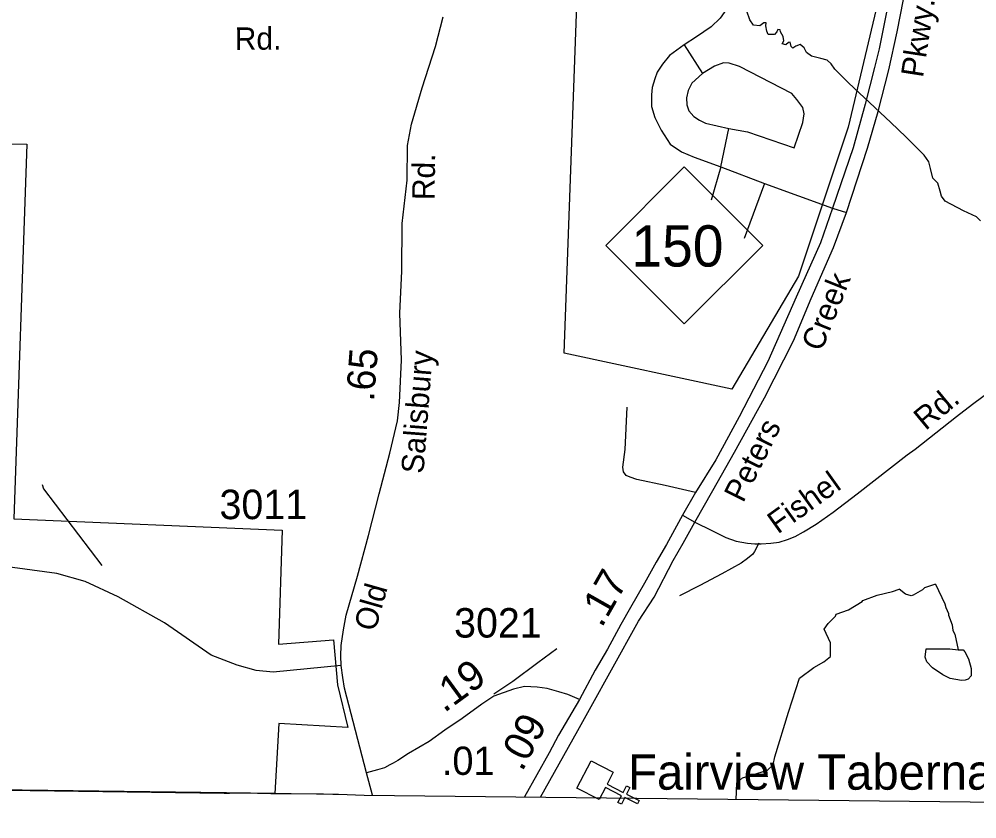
# Model space of a CAD drawing. Extents: x 1547597 to 1699558, y 810033 to 920809.
# Drawn here: x 1623103 to 1627167, y 819952 to 823344 of the extents above; entities that cross this region are included whole.
import ezdxf

# ---------------------------------------------------------------- set-up
doc = ezdxf.new("R2010")
doc.units = 0
for name, color, linetype in [('Exist Boundary Political City Limit New', 7, 'Continuous'), ('Exist Boundary Political CountyLine', 7, 'Continuous'), ('Exist Cultural Church CELL', 7, 'Continuous'), ('Exist Cultural Church Label', 7, 'Continuous'), ('Exist Hydrographic Creek Single Shore', 7, 'Continuous'), ('Exist Hydrographic Misc Water Feature', 7, 'Continuous'), ('Exist Road Non-System Type 51', 7, 'Continuous'), ('Exist Road Primary NC Divided Attributed', 7, 'Continuous'), ('Exist Road Primary NC Label', 7, 'Continuous'), ('Exist Road Primary NC Service Mileage Hundredths English Label', 7, 'Continuous'), ('Exist Road Primary NC Shield CELL', 7, 'Continuous'), ('Exist Road Primary NC Shield Number Label', 7, 'Continuous'), ('Exist Road Secondary Mileage Hundredths English Label', 7, 'Continuous'), ('Exist Road Secondary Type 51 Attributed', 7, 'Continuous'), ('Exist Road Secondary Type 51 Label', 7, 'Continuous'), ('Exist Road Secondary Type 51 Number Label', 7, 'Continuous'), ('Map Preparation Boundary City Limit Buffer Line', 7, 'Continuous')]:
    doc.layers.add(name, color=color, linetype=linetype)

msp = doc.modelspace()

# ---------------------------------------------------------------- linework, layer by layer
at = {"layer": 'Exist Boundary Political City Limit New'}
for points in [[(1624585.1, 825934.1), (1626899.2, 825873.3), (1626810, 823882.4), (1626744.7, 823409.9), (1626621.2, 822886.4), (1626410.5, 822253.9), (1626127.2, 821774), (1625415.4, 821926.7), (1625488, 823911.5), (1625546.1, 823940.6), (1625577.9, 824608.7), (1625332.2, 824717.2), (1625335.8, 825346.1), (1624345.6, 825299.1), (1624349.2, 825176.2), (1624287.8, 825349.7), (1624443.2, 825711.2), (1624585.1, 825934.1)], [(1622237.9, 822828.2), (1623135.5, 822813.7), (1623080, 821224.5), (1624219.3, 821176.2), (1624203.5, 820692.6), (1624436.5, 820710.6), (1624454.3, 820520.6), (1624498.1, 820339.4), (1624204.6, 820355.8), (1624188.1, 820058.9)], [(1624188.1, 820058.9), (1623982.5, 820061.2), (1621271.1, 820096.9)]]:
    msp.add_lwpolyline(points, dxfattribs=at)
at = {"layer": 'Exist Boundary Political CountyLine'}
msp.add_lwpolyline([(1606492.6, 820282.1), (1613860.9, 820194.5), (1614148.1, 820194.4), (1614278.7, 820193.7), (1614685.6, 820195), (1614832.4, 820191.9), (1615113.9, 820191.3), (1615321.1, 820189.2), (1615424.8, 820185.5), (1615839, 820171.5), (1623973.3, 820060), (1623995.2, 820060.7), (1624042.9, 820061.2), (1624114.1, 820060.5), (1624171.2, 820059.7), (1624213.4, 820059.1), (1624257.5, 820058.7), (1624364.8, 820057.3), (1624394.8, 820056.9), (1624433.9, 820056.2), (1624457.5, 820055.9), (1624566.7, 820052.4), (1633697.6, 819951.5)], dxfattribs=at)
at = {"layer": 'Exist Cultural Church CELL'}
msp.add_lwpolyline([(1625624.1, 820149.1), (1625598.1, 820098.4), (1625665.9, 820063.6), (1625680.5, 820092.1), (1625694.7, 820084.8), (1625680.1, 820056.3), (1625733.6, 820028.8), (1625726.2, 820014.6), (1625672.7, 820042), (1625658.1, 820013.6), (1625643.9, 820020.9), (1625658.5, 820049.3), (1625590.8, 820084.1), (1625564.4, 820032.9), (1625469.7, 820081.6), (1625529.4, 820197.7)], close=True, dxfattribs=at)
at = {"layer": 'Exist Hydrographic Creek Single Shore'}
for points in [[(1627182.1, 822488.9), (1627165.5, 822505.5), (1627110.6, 822531.5), (1627032.6, 822572.5), (1627017, 822593.5), (1627010.4, 822614.6), (1627001, 822647.8), (1626979.4, 822669.4), (1626970, 822710.9), (1626962.8, 822739.2), (1626942.8, 822767.4), (1626864.8, 822844.4), (1626802.2, 822905.3), (1626622.2, 823074.2), (1626564.6, 823131.3), (1626548, 823154.5), (1626531.4, 823169.5), (1626504.2, 823177.8), (1626464.4, 823187.8), (1626443.3, 823202.2), (1626433.4, 823222.6), (1626416.7, 823236.5), (1626399, 823229.3), (1626385.2, 823221.5), (1626379.1, 823227.6), (1626374.1, 823245.9), (1626366.9, 823244.8), (1626356.4, 823234.8), (1626340.9, 823239.8), (1626348.1, 823252), (1626345.3, 823270.3), (1626333.7, 823290.2), (1626331.5, 823299.1), (1626322.6, 823300.7), (1626317.6, 823290.2), (1626307.7, 823279.1), (1626281.6, 823279.7), (1626275.5, 823293), (1626271.1, 823316.2), (1626272.2, 823328.4), (1626262.2, 823328.4), (1626245.6, 823316.2), (1626219, 823319), (1626203, 823340.6), (1626190.8, 823377.7)], [(1623199.8, 821369.5), (1623206.7, 821351.4), (1623453.1, 821025.6)]]:
    msp.add_lwpolyline(points, dxfattribs=at)
at = {"layer": 'Exist Hydrographic Misc Water Feature'}
for points in [[(1626144.9, 820032.7), (1626148.1, 820103.7), (1626172.8, 820125.5), (1626232.5, 820144.4), (1626279, 820157.5), (1626302.3, 820180.8), (1626309.8, 820215), (1626367.8, 820404.4), (1626413.7, 820548), (1626474.8, 820593.8), (1626517.6, 820618.2), (1626545.1, 820639.6), (1626545.1, 820697.7), (1626519.4, 820756.7), (1626535.8, 820780.4), (1626566.3, 820811.9), (1626570.4, 820819.8), (1626622.7, 820838.8), (1626680.6, 820873.1), (1626683.4, 820877.7), (1626743.8, 820900.6), (1626808.1, 820915.5), (1626837.3, 820926.1)], [(1626990.6, 820946.9), (1626944.3, 820931), (1626936.2, 820923.1), (1626895.8, 820899.9), (1626887.7, 820898), (1626863.9, 820904.5), (1626837.3, 820926.1)], [(1626990.6, 820946.9), (1627031.2, 820863.5), (1627035, 820847.5), (1627046.6, 820823.3), (1627046.5, 820815.3), (1627061.7, 820775), (1627065.3, 820751), (1627073.1, 820734.9), (1627086.8, 820668.4)], [(1627086.8, 820668.4), (1627108, 820668.3), (1627115.9, 820660.2), (1627131.3, 820629.9), (1627142.7, 820589.8), (1627142.1, 820557.8), (1627129.9, 820544.1), (1627117.8, 820540.3), (1627101.8, 820538.6), (1627053.9, 820547.4), (1627022.2, 820561.9), (1626978.7, 820592.7), (1626955.1, 820617.1), (1626947.4, 820637.2), (1626951, 820672.8), (1626964, 820672.9), (1627052.1, 820673.3), (1627086.8, 820668.4)]]:
    msp.add_lwpolyline(points, dxfattribs=at)
at = {"layer": 'Exist Road Non-System Type 51'}
for p, q in [((1625925.3, 823235.8), (1626002.7, 823113.5)), ((1626080.2, 822717.9), (1626113.8, 822880.6)), ((1626080.2, 822717.9), (1626039.8, 822576.5)), ((1626080.2, 822717.9), (1626265.3, 822647.2)), ((1626265.3, 822647.2), (1626178.9, 822413.7)), ((1626265.3, 822647.2), (1626554.6, 822542)), ((1626554.6, 822542), (1626613.9, 822523.8))]:
    msp.add_line(p, q, dxfattribs=at)
for points in [[(1626208.1, 823601.1), (1626141.9, 823463.1), (1626104.8, 823386.8), (1626077.9, 823348.6), (1626038.6, 823311.6), (1625976.9, 823269.5), (1625925.3, 823235.8)], [(1625925.3, 823235.8), (1625862.4, 823189.8), (1625832.1, 823152.8), (1625810.8, 823119.1), (1625800.7, 823091), (1625789.5, 823054), (1625786.1, 823023.7), (1625786.1, 822974.3), (1625799.6, 822926.6), (1625826.5, 822872.8), (1625864.7, 822813.3)], [(1626392.1, 822798.7), (1626428.1, 822905.9), (1626433.7, 822941.8), (1626428.1, 822969.8), (1626403.4, 823003.5), (1626382, 823028.2), (1626159.8, 823142.7), (1626115, 823157.2), (1626091.4, 823158.4), (1626053.2, 823144.9), (1626002.7, 823113.5)], [(1626002.7, 823113.5), (1625956.7, 823072.5), (1625941, 823041.1), (1625934.3, 823010.8), (1625935.4, 822980.5), (1625944.4, 822955.8), (1625965.7, 822931.1), (1625990.4, 822915.4), (1626015.1, 822903.1), (1626113.8, 822880.6)], [(1626113.8, 822880.6), (1626193.5, 822866), (1626392.1, 822798.7)], [(1625864.7, 822813.3), (1625912.9, 822781.8), (1625966.8, 822758.3), (1626080.2, 822717.9)], [(1625972.1, 821335.4), (1625844.6, 821365.3), (1625724, 821391.2), (1625694.9, 821400.4), (1625678.1, 821408), (1625667.4, 821423.3), (1625664.4, 821443.2), (1625674.3, 821518), (1625683.5, 821698.3)], [(1626242.2, 821121.2), (1626223.1, 821086.1), (1626216.8, 821073.8), (1626192.8, 821055.4), (1626167.2, 821036.1), (1626084.4, 820991.3), (1625991.8, 820940.8), (1625905.1, 820898.1)], [(1624469.1, 820601.6), (1624180.2, 820574.4), (1624108.3, 820581.1), (1624027.5, 820603.5), (1623917.6, 820646.2), (1623720, 820783.1), (1623522.5, 820893.1), (1623383.4, 820958.2), (1623262.2, 820991.8), (1623022, 821025.5)], [(1625116.6, 820482.5), (1625197.6, 820535.3), (1625303.2, 820614.2), (1625383.8, 820673.8)]]:
    msp.add_lwpolyline(points, dxfattribs=at)
at = {"layer": 'Exist Road Primary NC Divided Attributed'}
for points in [[(1625969.8, 821210.2), (1626046.3, 821344.8), (1626138.2, 821507.6), (1626265, 821737.4), (1626388, 821979.4), (1626463.8, 822159.4), (1626559.1, 822375.4), (1626613.9, 822523.8), (1626703.1, 822796.2), (1626747.9, 822953), (1626792.8, 823129.1), (1626828.2, 823290.2), (1626868.1, 823494.6), (1626907.4, 823776.4), (1626926.2, 823925.4), (1626935.1, 824050), (1626956.7, 824516.8), (1626989.2, 825152.1), (1627009.8, 825594.5), (1627038.6, 826219.7), (1627059.1, 826636.7), (1627088.5, 827252)], [(1627021.5, 827250.3), (1627004.3, 826710.9), (1626949.5, 825591.7), (1626930.1, 825208), (1626896.9, 824515.2), (1626847.6, 823786.9), (1626799.5, 823454.6), (1626782.2, 823366.1), (1626752.3, 823218.8), (1626731.8, 823139.6), (1626693.1, 822983.4), (1626642.1, 822797.9), (1626554.6, 822542), (1626503.1, 822395.3), (1626400.1, 822164.4), (1626279.4, 821891.9), (1626157.6, 821657.1), (1626059, 821474.4), (1625972.1, 821335.4), (1625918.3, 821239.5)], [(1625918.3, 821239.5), (1625849.1, 821114.9), (1625806.5, 821040.2), (1625756.1, 820951.6), (1625697.4, 820848), (1625656.4, 820775.5), (1625599.4, 820671.4), (1625546.8, 820582.8), (1625480.9, 820458.2)], [(1625530.7, 820427.7), (1625616, 820583.3), (1625730.6, 820790.4), (1625797, 820892.1), (1625878.5, 821047.4), (1625920, 821120.5), (1625969.8, 821210.2)], [(1625480.9, 820458.2), (1625448.7, 820403.3), (1625391.1, 820306.4), (1625351.8, 820231.7), (1625246.6, 820044.8)], [(1625314.4, 820044.1), (1625473.7, 820326.9), (1625530.7, 820427.7)]]:
    msp.add_lwpolyline(points, dxfattribs=at)
at = {"layer": 'Exist Road Primary NC Shield CELL'}
msp.add_lwpolyline([(1625592, 822384.2), (1625925, 822717.2), (1626258, 822384.2), (1625925, 822051.2)], close=True, dxfattribs=at)
at = {"layer": 'Exist Road Secondary Type 51 Attributed'}
for points in [[(1624576.4, 820146.4), (1624484, 820506.3), (1624476.3, 820551.7), (1624469.1, 820601.6), (1624467.4, 820642.6), (1624469.1, 820686.9), (1624478.5, 820753.3), (1624490.7, 820815.9), (1624538.3, 820980.9), (1624585.9, 821153.2), (1624630.8, 821330.9), (1624676.2, 821502.5), (1624707.6, 821639.4), (1624716.6, 821717.9), (1624725.6, 821897.5), (1624717.8, 822097.3), (1624726.4, 822275.1), (1624727.5, 822476.9), (1624748.7, 822660.6), (1624750.9, 822808.4), (1624768.2, 822898.6), (1624813.1, 823053.4), (1624869.2, 823228.5), (1624902.7, 823354.4)], [(1625969.8, 821210.2), (1626041.9, 821174.9), (1626102.2, 821145.4), (1626145.9, 821129.3), (1626193.6, 821121), (1626225.1, 821117.7), (1626251.7, 821118.8), (1626292.1, 821120.5), (1626327.6, 821125.5), (1626362.5, 821136), (1626395.7, 821149.3), (1626431.1, 821169.2), (1626484.3, 821201.3), (1626556.9, 821252.8), (1626658.8, 821330.9), (1626871.4, 821495.9), (1626904.6, 821520.3), (1627080.7, 821658.8), (1627147.9, 821710.2), (1627274.6, 821804.4)], [(1625918.3, 821239.5), (1625969.8, 821210.2)], [(1625480.9, 820458.2), (1625431.1, 820479.3), (1625392.6, 820489.8), (1625343.5, 820503.8), (1625301.5, 820510.8), (1625247.2, 820512.6), (1625201.1, 820501.9), (1625116.6, 820471.6), (1625065.7, 820438.1), (1624982.9, 820377.6), (1624909.7, 820327.8), (1624842.1, 820280.2), (1624754.7, 820228.1), (1624710.1, 820199.3), (1624690.2, 820187.1), (1624675.1, 820180), (1624652.8, 820168.5), (1624622.9, 820159.2), (1624576.4, 820146.4)], [(1624601.5, 820052), (1624576.4, 820146.4)]]:
    msp.add_lwpolyline(points, dxfattribs=at)
at = {"layer": 'Map Preparation Boundary City Limit Buffer Line'}
for points in [[(1624585.1, 825934.1), (1626899.2, 825873.3), (1626810, 823882.4), (1626744.7, 823409.9), (1626621.2, 822886.4), (1626410.5, 822253.9), (1626127.2, 821774), (1625415.4, 821926.7), (1625488, 823911.5), (1625546.1, 823940.6), (1625577.9, 824608.7), (1625332.2, 824717.2), (1625335.8, 825346.1), (1624345.6, 825299.1), (1624349.2, 825176.2), (1624287.8, 825349.7), (1624443.2, 825711.2), (1624585.1, 825934.1)], [(1622237.9, 822828.2), (1623135.5, 822813.7), (1623080, 821224.5), (1624219.3, 821176.2), (1624203.5, 820692.6), (1624436.5, 820710.6), (1624454.3, 820520.6), (1624498.1, 820339.4), (1624204.6, 820355.8), (1624188.1, 820058.9)], [(1624188.1, 820058.9), (1623982.5, 820061.2), (1621271.1, 820096.9)]]:
    msp.add_lwpolyline(points, dxfattribs=at)

# ---------------------------------------------------------------- texts
at = {"layer": 'Exist Cultural Church Label'}
msp.add_text('Fairview Tabernacle', height=150, dxfattribs=at).set_placement((1625686.9, 820075.2))
at = {"layer": 'Exist Road Primary NC Label'}
for s, rotation, p in [('Pkwy.', 81.2247, (1626937.8, 823093.3)), ('Creek', 68.1713, (1626507, 821929.9)), ('Peters', 63.5601, (1626174.8, 821288.7))]:
    msp.add_text(s, height=95, rotation=rotation, dxfattribs=at).set_placement(p)
at = {"layer": 'Exist Road Primary NC Service Mileage Hundredths English Label'}
for s, rotation, p in [('.17', 60.4535, (1625574.8, 820758.6)), ('.09', 62.259, (1625237.4, 820148.3))]:
    msp.add_text(s, height=125, rotation=rotation, dxfattribs=at).set_placement(p)
at = {"layer": 'Exist Road Primary NC Shield Number Label'}
msp.add_text('150', height=175, dxfattribs=at).set_placement((1625701.1, 822294.5))
at = {"layer": 'Exist Road Secondary Mileage Hundredths English Label'}
for s, height, rotation, p in [('.65', 120, 85.6226, (1624608.3, 821720.6)), ('.19', 125, 36.1796, (1624906.3, 820399))]:
    msp.add_text(s, height=height, rotation=rotation, dxfattribs=at).set_placement(p)
msp.add_text('.01', height=120, dxfattribs=at).set_placement((1624896.8, 820137.9))
at = {"layer": 'Exist Road Secondary Type 51 Label'}
for s, rotation, p in [('Rd.', 0.4246, (1624018.1, 823213.7)), ('Rd.', 89.1481, (1624865.4, 822575.9)), ('Salisbury', 85.6226, (1624818.4, 821413.6)), ('Rd.', 39.6819, (1626948.8, 821596.4)), ('Fishel', 35.6073, (1626322, 821157.4)), ('Old', 74.0922, (1624613.2, 820742.4))]:
    msp.add_text(s, height=95, rotation=rotation, dxfattribs=at).set_placement(p)
at = {"layer": 'Exist Road Secondary Type 51 Number Label'}
for s, p in [('3011', (1623952.9, 821222.9)), ('3021', (1624948.3, 820720.5))]:
    msp.add_text(s, height=125, dxfattribs=at).set_placement(p)

doc.saveas('drawing.dxf')
